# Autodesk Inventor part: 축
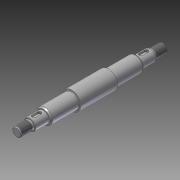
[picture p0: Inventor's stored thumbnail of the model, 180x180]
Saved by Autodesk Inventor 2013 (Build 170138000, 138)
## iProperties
Created: 2018-11
Part Number: 축
Material: 강철, 연강
Document SubType Name: Modeling
Designer: mduedu
Density: 1 g/cm^3
Author: mduedu
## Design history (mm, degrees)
sketch "스케치1"
  geometry: L1 (-24, 0)-(24, 0); L2 (24, 0)-(24, 12); L3 (24, 12)-(-24, 12); L4 (-24, 12)-(-24, 0); L5 (-24, 0)-(-79, 0); L6 (-79, 0)-(-79, 7.5); L7 (-79, 7.5)-(-61, 7.5); L8 (-24, 7.5)-(-24, 0); L9 (-79, 0)-(-96, 0); L10 (-96, 0)-(-96, 6); L11 (-96, 6)-(-79, 6); L12 (-79, 6)-(-79, 0); L13 (0, 0)-(0, 12); L14 (24, 0)-(79, 0); L15 (79, 0)-(79, 7.5); L16 (79, 7.5)-(61, 7.5); L17 (24, 7.5)-(24, 0); L18 (79, 0)-(96, 0); L19 (96, 0)-(96, 6); L20 (96, 6)-(79, 6); L21 (79, 6)-(79, 0); L22 (-61, 7.5)-(-61, 8.85); L23 (-59.008, 10)-(-24, 10); L24 (24, 10)-(59.008, 10); L25 (61, 8.85)-(61, 7.5); L26 (-61, 8.85)-(-59.008, 10); L27 (61, 8.85)-(59.008, 10); 1 further point
  constraints: 54 end point, 9 parallel, 6 symmetric about line, 4 horizontal, 4 perpendicular, 2 midpoint, 2 point on line, 1 coincident
  dimensions: "d0" = 24 diameter of L3 L1; "d2" = 15 diameter of L7 L5; "d3" = 12 diameter of L11 L9; "d4" = 48 distance of L2.end L3.end; "d5" = 55 distance of L6.end L8.start; "d6" = 192 distance between parallel lines of L19 L10; "d24" = 20 diameter of L23 L5; "d25" = 18 distance of L6.end L7.end; "d26" = 18 distance of L15.end L16.end; "d27" = 20 diameter of L24 L14; "d28" = 55 distance between parallel lines of L15 L2; "d29" = 30 deg angle of L23 L26; "d30" = 17.7 diameter of L22.end L5; "d31" = 30 deg angle of L24 L27; "d32" = 17.7 diameter of L25.start L14
revolve "회전1" sketch "스케치1" stored, may be unused: angle "d7" = 90 deg
fillet "모깎기1" dims "d8" = 0.6
node "작업 평면1"
sketch "스케치2" dims "d11" = 12
  geometry: L1 (-3.5, 2.5)-(3.5, 2.5); L2 (3.5, 2.5)-(3.5, -2.5); L3 (3.5, -2.5)-(-3.5, -2.5); L4 (-3.5, -2.5)-(-3.5, 2.5); L5 (9, 7.5)-(9, -7.5) reference; 3 further points
  constraints: 8 end point, 2 midpoint, 2 parallel, 2 vertical alignment, 1 horizontal, 1 horizontal alignment, 1 perpendicular, 4 other
  dimensions: "d9" = 3 dimension on L5; "d10" = 5 distance between parallel lines of L3 L1
extrude "돌출1" cut sketch "스케치2" distance "d12" = 3; taper "d13" = 0 deg
chamfer "모따기1" distance "d14" = 0.5; stored, may be unused: second distance "d15" = 2, angle "d16" = 45 deg
feature "스레드1" dims "d17" = 15, "d18" = 0
feature "스레드2" dims "d19" = 15, "d20" = 0
chamfer "모따기2" distance "d21" = 1; stored, may be unused: second distance "d22" = 2, angle "d23" = 45 deg
node "솔리드1"
mirror "대칭1"
